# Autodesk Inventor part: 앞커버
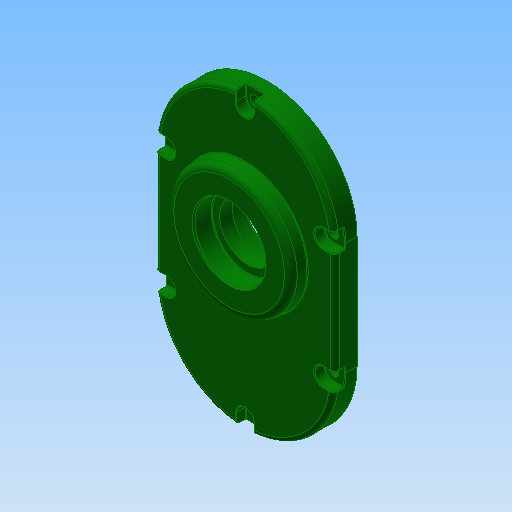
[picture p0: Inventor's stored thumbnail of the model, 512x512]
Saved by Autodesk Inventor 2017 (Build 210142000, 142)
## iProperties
Created: 2016-12
Part Number: 앞커버
Material: 알루미늄 6061
Document SubType Name: Modeling
Designer: mduedu
Density: 2.71 g/cm^3
Appearance: 진녹색
Mass: 262.268 g
Surface Area: 259.904 cm^2
Volume: 96.7777 cm^3
Author: mduedu
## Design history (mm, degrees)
sketch "스케치1"
  geometry: L1 (40, -25)-(40, 25); L2 (-40, 25)-(-40, -25); L3 (-40, -25)-(40, 25); L4 (40, -25)-(-40, 25); A1 r 40 centre (0, 25) between (40, 25) and (-40, 25); A2 r 40 centre (0, -25) between (-40, -25) and (40, -25); 1 further point
  constraints: 8 end point, 4 point on circle, 4 tangent, 2 centre point, 2 midpoint, 1 parallel, 1 vertical
  dimensions: "d0" = 130 dimension on A2 A1; "d2" = 80 distance between parallel lines of L1 L2
extrude "돌출1" new body sketch "스케치1" distance "d3" = 10; taper "d4" = 0 deg
sketch "스케치2"
  geometry: C1 r 21 at (0, 11); 1 further point
  constraints: 1 centre point, 1 vertical alignment
  dimensions: "d5" = 42 diameter of C1; "d7" = 11 distance of C1.centre point (0, 0)
extrude "돌출2" join sketch "스케치2" distance "d8" = 7; taper "d9" = 0 deg
sketch "스케치3"
  geometry: C1 r 15 at (0, -33.1); C2 r 21 at (0, 11) reference; 1 further point
  constraints: 1 centre point, 1 vertical alignment
  dimensions: "d10" = 30 diameter of C1; "d71" = 44.1 distance of C1.centre C2.centre
extrude "돌출3" join sketch "스케치3" distance "d12" = 7; taper "d13" = 0 deg
sketch "스케치4"
  geometry: C1 r 28 at (0, 11); A1 r 21 centre (0, 11) between (8.978, -7.984) and (-8.978, -7.984) reference; 1 further point
  constraints: 1 centre point, 1 coincident
  dimensions: "d14" = 56 diameter of C1
extrude "돌출4" join sketch "스케치4" distance "d15" = 7; taper "d16" = -5 deg
hole "구멍1" diameter "d19" = 35; stored, may be unused: countersink angle "d23" = 90 deg, drill point angle "d25" = 0 deg; dims "d17" = 10, "d18" = 10, "d20" = 6, "d21" = 4, "d22" = 2, "d24" = 10
hole "구멍2" diameter "d28" = 22; stored, may be unused: countersink angle "d32" = 90 deg, drill point angle "d34" = 0 deg; dims "d26" = 10, "d27" = 10, "d29" = 6, "d30" = 4, "d31" = 2, "d33" = 7
hole "구멍3" diameter "d37" = 19; stored, may be unused: countersink angle "d41" = 90 deg, drill point angle "d43" = 0 deg; dims "d38" = 6, "d39" = 4, "d40" = 2, "d42" = 2, "d108" = 10, "d109" = 10
hole "구멍4" diameter "d46" = 32; stored, may be unused: countersink angle "d50" = 90 deg, drill point angle "d52" = 0 deg; dims "d47" = 6, "d48" = 4, "d49" = 2, "d51" = 8.3, "d101" = 10, "d102" = 10
hole "구멍5" diameter "d55" = 25; stored, may be unused: countersink angle "d59" = 90 deg, drill point angle "d61" = 0 deg; dims "d53" = 10, "d54" = 10, "d56" = 6, "d57" = 4, "d58" = 2, "d60" = 8
fillet "모깎기1" dims "d62" = 0.3
fillet "모깎기2" dims "d63" = 2
chamfer "모따기1" distance "d64" = 0.8; stored, may be unused: second distance "d65" = 2, angle "d66" = 30 deg
fillet "모깎기4" dims "d68" = 2
fillet "모깎기5" dims "d69" = 0.3
fillet "모깎기6" dims "d70" = 2
sketch "스케치5"
  geometry: L1 (-40, 25)-(-40, -25) reference; L2 (40, -25)-(40, 25) reference; L3 (35, 25)-(35, -25); L4 (-35, -25)-(-35, 25); A1 r 40 centre (0, 25) between (40, 25) and (-40, 25) reference; A2 r 40 centre (0, -25) between (-40, -25) and (40, -25) reference; A3 r 35 centre (0, 25) between (35, 25) and (-35, 25); A4 r 35 centre (0, -25) between (-35, -25) and (35, -25); 2 further points
  constraints: 5 point on circle, 4 end point, 2 centre point, 1 vertical alignment, 3 other
  dimensions: "d72" = 5 distance between parallel lines of L2 L3
sketch "스케치7"
  geometry: 1 further point
hole "구멍7" sketch "스케치7" at (0, 60) diameter "d80" = 4.5; stored, may be unused: countersink angle "d84" = 90 deg, drill point angle "d86" = 0 deg; dims "d81" = 6, "d82" = 8, "d83" = 4.6, "d85" = 8
sketch "스케치9"
  geometry: L1 (-4, 0)-(4, 0); L2 (4, 0)-(4, 5); L3 (4, 5)-(-4, 5); L4 (-4, 5)-(-4, 0); C1 r 2.25 at (0, 0) reference; A1 r 40 centre (0, -35) between (40, -35) and (-40, -35) reference; 2 further points
  constraints: 8 end point, 2 parallel, 2 vertical, 1 horizontal, 1 horizontal alignment, 1 perpendicular, 1 tangent, 1 other
extrude "돌출6" cut sketch "스케치9" stored distance "d96" = 3; taper "d97" = 0 deg
fillet "모깎기7" dims "d98" = 0.3
fillet "모깎기8" dims "d99" = 0.3
fillet "모깎기9" dims "d100" = 3
chamfer "모따기3" distance "d103" = 1; stored, may be unused: second distance "d104" = 2, angle "d105" = 45 deg
node "솔리드1"
pattern_linear "직사각형 패턴1"
node "투영된 루프1"
